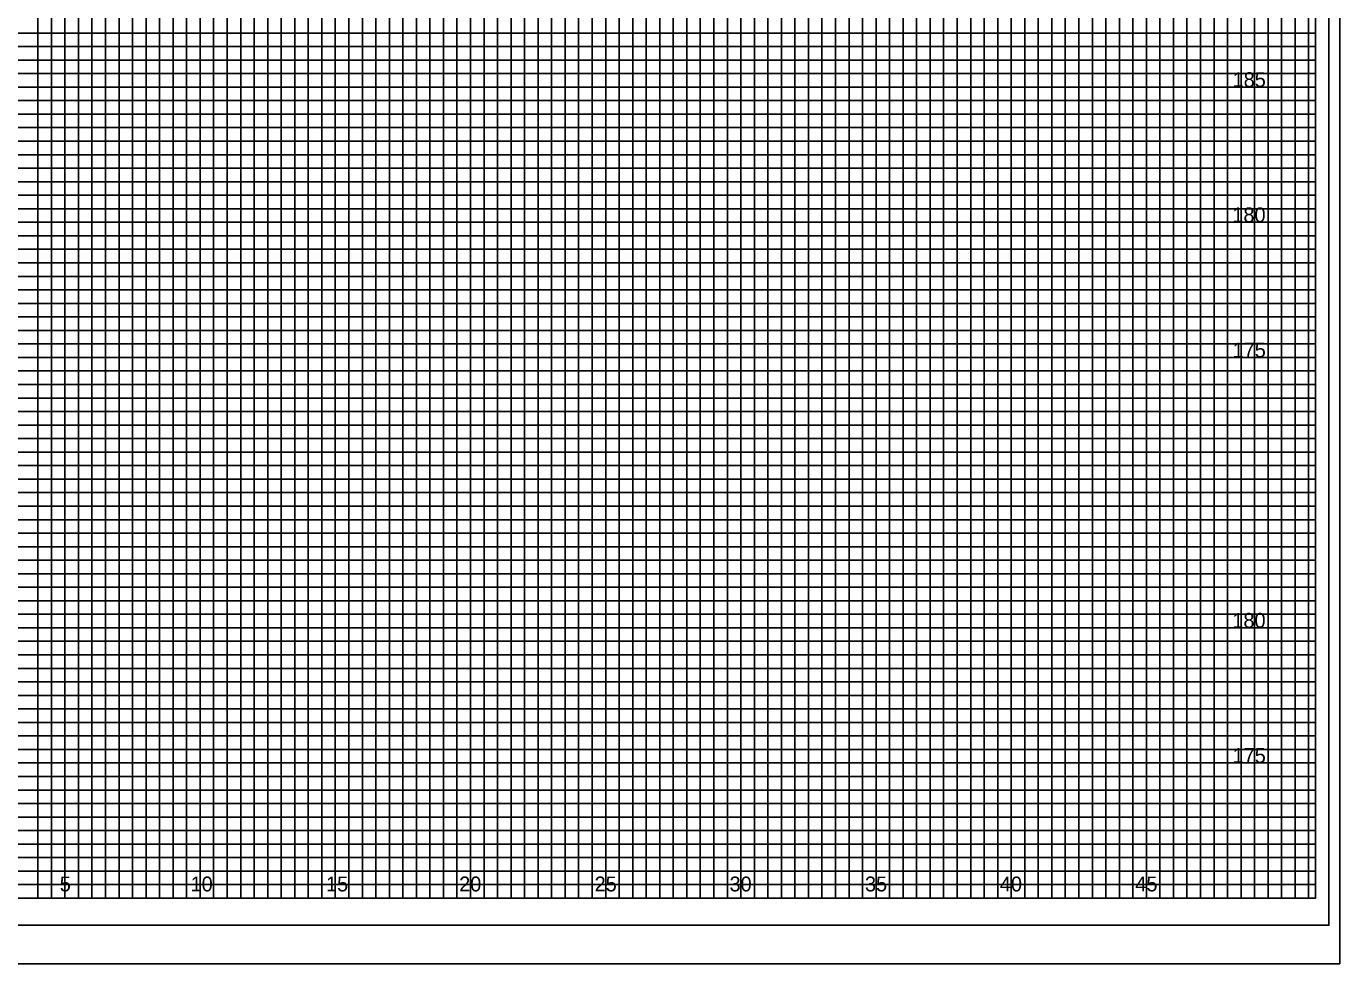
# Model space of a CAD drawing. Extents: x -4 to 103, y -2 to 138.
# Drawn here: x 54.82 to 103.4, y 68.4 to 103.08 of the extents above; entities that cross this region are included whole.
import ezdxf

# ---------------------------------------------------------------- set-up
doc = ezdxf.new("R2010")
doc.units = 0
for name, color, linetype in [('Old_Level_10', 7, 'Continuous'), ('Old_Level_3', 7, 'Continuous'), ('Old_Level_4', 7, 'Continuous'), ('Old_Level_5', 7, 'Continuous'), ('Old_Level_8', 7, 'Continuous'), ('Prop XS Elevation Labels', 7, 'Continuous'), ('Prop XS EOT Tick Mark', 7, 'Continuous'), ('Prop XS Finish Grade', 7, 'Continuous'), ('Prop XS Finish Grade Pavement', 7, 'Continuous')]:
    doc.layers.add(name, color=color, linetype=linetype)

msp = doc.modelspace()

# ---------------------------------------------------------------- linework, layer by layer
at = {"layer": 'Old_Level_10'}
for p, q in [((56.25, 70.825), (56.25, 135.825)), ((58.75, 70.825), (58.75, 135.825)), ((61.25, 70.825), (61.25, 135.825)), ((63.75, 70.825), (63.75, 135.825)), ((66.25, 70.825), (66.25, 135.825)), ((68.75, 70.825), (68.75, 135.825)), ((71.25, 70.825), (71.25, 135.825)), ((73.75, 70.825), (73.75, 135.825)), ((91.25, 70.825), (91.25, 134.25)), ((93.75, 70.825), (93.75, 134.25)), ((96.25, 70.825), (96.25, 134.25)), ((98.75, 70.825), (98.75, 134.25)), ((101.25, 70.825), (101.25, 134.25)), ((76.25, 70.825), (76.25, 132.825)), ((78.75, 70.825), (78.75, 132.825)), ((81.25, 70.825), (81.25, 132.825)), ((83.75, 70.825), (83.75, 132.825)), ((86.25, 70.825), (86.25, 132.825)), ((88.75, 70.825), (88.75, 132.825)), ((0, 100.825), (102.5, 100.825)), ((0, 98.325), (102.5, 98.325)), ((0, 95.825), (102.5, 95.825)), ((0, 93.325), (102.5, 93.325)), ((0, 90.825), (102.5, 90.825)), ((0, 88.325), (102.5, 88.325)), ((0, 85.825), (102.5, 85.825)), ((0, 83.325), (102.5, 83.325)), ((0, 80.825), (102.5, 80.825)), ((0, 78.325), (102.5, 78.325)), ((0, 75.825), (102.5, 75.825)), ((0, 73.325), (102.5, 73.325))]:
    msp.add_line(p, q, dxfattribs=at)
at = {"layer": 'Old_Level_3'}
msp.add_line((-3.5, 68.4), (103.4, 68.4), dxfattribs=at)
at = {"layer": 'Old_Level_4'}
msp.add_lwpolyline([(103, 136.825), (-2.8, 136.825), (-2.8, 69.825), (103, 69.825)], close=True, dxfattribs=at)
at = {"layer": 'Old_Level_5'}
msp.add_lwpolyline([(103.4, 138.225), (-3.5, 138.225), (-3.5, 68.4), (103.4, 68.4)], close=True, dxfattribs=at)
at = {"layer": 'Old_Level_8'}
for points in [[(56.25, 70.825), (56.25, 135.825)], [(58.75, 135.825), (58.75, 70.825), (61.25, 70.825), (61.25, 135.825)], [(63.75, 135.825), (63.75, 70.825), (66.25, 70.825), (66.25, 135.825)], [(68.75, 135.825), (68.75, 70.825), (71.25, 70.825), (71.25, 135.825)], [(73.75, 135.825), (73.75, 70.825), (76.25, 70.825), (76.25, 132.825)], [(88.75, 132.825), (88.75, 70.825), (91.25, 70.825), (91.25, 134.25)], [(93.75, 134.25), (93.75, 70.825), (96.25, 70.825), (96.25, 134.25)], [(98.75, 134.25), (98.75, 70.825), (101.25, 70.825), (101.25, 134.25)], [(78.75, 132.825), (78.75, 70.825), (81.25, 70.825), (81.25, 132.825)], [(83.75, 132.825), (83.75, 70.825), (86.25, 70.825), (86.25, 132.825)], [(0, 98.325), (102.5, 98.325), (102.5, 100.825), (0, 100.825)], [(0, 93.325), (102.5, 93.325), (102.5, 95.825), (0, 95.825)], [(0, 88.325), (102.5, 88.325), (102.5, 90.825), (0, 90.825)], [(0, 83.325), (102.5, 83.325), (102.5, 85.825), (0, 85.825)], [(0, 78.325), (102.5, 78.325), (102.5, 80.825), (0, 80.825)], [(0, 73.325), (102.5, 73.325), (102.5, 75.825), (0, 75.825)]]:
    msp.add_lwpolyline(points, dxfattribs=at)
at = {"layer": 'Prop XS Elevation Labels'}
msp.add_lwpolyline([(102.5, 135.825), (0, 135.825), (0, 70.825), (102.5, 70.825)], close=True, dxfattribs=at)
at = {"layer": 'Prop XS Finish Grade'}
for points in [[(54.75, 70.825), (55.25, 70.825), (55.25, 135.825)], [(55.75, 135.825), (55.75, 70.825), (56.75, 70.825), (56.75, 135.825)], [(57.25, 135.825), (57.25, 70.825), (57.75, 70.825), (57.75, 135.825)], [(58.25, 135.825), (58.25, 70.825), (59.25, 70.825), (59.25, 135.825)], [(59.75, 135.825), (59.75, 70.825), (60.25, 70.825), (60.25, 135.825)], [(60.75, 135.825), (60.75, 70.825), (61.75, 70.825), (61.75, 135.825)], [(62.25, 135.825), (62.25, 70.825), (62.75, 70.825), (62.75, 135.825)], [(63.25, 135.825), (63.25, 70.825), (64.25, 70.825), (64.25, 135.825)], [(64.75, 135.825), (64.75, 70.825), (65.25, 70.825), (65.25, 135.825)], [(65.75, 135.825), (65.75, 70.825), (66.75, 70.825), (66.75, 135.825)], [(67.25, 135.825), (67.25, 70.825), (67.75, 70.825), (67.75, 135.825)], [(68.25, 135.825), (68.25, 70.825), (69.25, 70.825), (69.25, 135.825)], [(69.75, 135.825), (69.75, 70.825), (70.25, 70.825), (70.25, 135.825)], [(70.75, 135.825), (70.75, 70.825), (71.75, 70.825), (71.75, 135.825)], [(72.25, 135.825), (72.25, 70.825), (72.75, 70.825), (72.75, 135.825)], [(73.25, 135.825), (73.25, 70.825), (74.25, 70.825), (74.25, 132.825)], [(89.75, 132.825), (89.75, 70.825), (90.25, 70.825), (90.25, 134.25)], [(90.75, 134.25), (90.75, 70.825), (91.75, 70.825), (91.75, 134.25)], [(92.25, 134.25), (92.25, 70.825), (92.75, 70.825), (92.75, 134.25)], [(93.25, 134.25), (93.25, 70.825), (94.25, 70.825), (94.25, 134.25)], [(94.75, 134.25), (94.75, 70.825), (95.25, 70.825), (95.25, 134.25)], [(95.75, 134.25), (95.75, 70.825), (96.75, 70.825), (96.75, 134.25)], [(97.25, 134.25), (97.25, 70.825), (97.75, 70.825), (97.75, 134.25)], [(98.25, 134.25), (98.25, 70.825), (99.25, 70.825), (99.25, 134.25)], [(99.75, 134.25), (99.75, 70.825), (100.25, 70.825), (100.25, 134.25)], [(100.25, 134.25), (100.75, 134.25), (100.75, 70.825), (101.75, 70.825), (101.75, 134.25), (102.25, 134.25), (102.25, 70.825)], [(74.75, 132.825), (74.75, 70.825), (75.25, 70.825), (75.25, 132.825)], [(75.75, 132.825), (75.75, 70.825), (76.75, 70.825), (76.75, 132.825)], [(77.25, 132.825), (77.25, 70.825), (77.75, 70.825), (77.75, 132.825)], [(78.25, 132.825), (78.25, 70.825), (79.25, 70.825), (79.25, 132.825)], [(79.75, 132.825), (79.75, 70.825), (80.25, 70.825), (80.25, 132.825)], [(80.75, 132.825), (80.75, 70.825), (81.75, 70.825), (81.75, 132.825)], [(82.25, 132.825), (82.25, 70.825), (82.75, 70.825), (82.75, 132.825)], [(83.25, 132.825), (83.25, 70.825), (84.25, 70.825), (84.25, 132.825)], [(84.75, 132.825), (84.75, 70.825), (85.25, 70.825), (85.25, 132.825)], [(85.75, 132.825), (85.75, 70.825), (86.75, 70.825), (86.75, 132.825)], [(87.25, 132.825), (87.25, 70.825), (87.75, 70.825), (87.75, 132.825)], [(88.25, 132.825), (88.25, 70.825), (89.25, 70.825), (89.25, 132.825)], [(0, 102.325), (102.5, 102.325), (102.5, 102.825), (0, 102.825)], [(0, 101.325), (102.5, 101.325), (102.5, 101.825), (0, 101.825)], [(0, 99.825), (102.5, 99.825), (102.5, 100.325), (0, 100.325)], [(0, 98.825), (102.5, 98.825), (102.5, 99.325), (0, 99.325)], [(0, 97.325), (102.5, 97.325), (102.5, 97.825), (0, 97.825)], [(0, 96.325), (102.5, 96.325), (102.5, 96.825), (0, 96.825)], [(0, 94.825), (102.5, 94.825), (102.5, 95.325), (0, 95.325)], [(0, 93.825), (102.5, 93.825), (102.5, 94.325), (0, 94.325)], [(0, 92.325), (102.5, 92.325), (102.5, 92.825), (0, 92.825)], [(0, 91.325), (102.5, 91.325), (102.5, 91.825), (0, 91.825)], [(0, 89.825), (102.5, 89.825), (102.5, 90.325), (0, 90.325)], [(0, 88.825), (102.5, 88.825), (102.5, 89.325), (0, 89.325)], [(0, 87.325), (102.5, 87.325), (102.5, 87.825), (0, 87.825)], [(0, 86.325), (102.5, 86.325), (102.5, 86.825), (0, 86.825)], [(0, 84.825), (102.5, 84.825), (102.5, 85.325), (0, 85.325)], [(0, 83.825), (102.5, 83.825), (102.5, 84.325), (0, 84.325)], [(0, 82.325), (102.5, 82.325), (102.5, 82.825), (0, 82.825)], [(0, 81.325), (102.5, 81.325), (102.5, 81.825), (0, 81.825)], [(0, 79.825), (102.5, 79.825), (102.5, 80.325), (0, 80.325)], [(0, 78.825), (102.5, 78.825), (102.5, 79.325), (0, 79.325)], [(0, 77.325), (102.5, 77.325), (102.5, 77.825), (0, 77.825)], [(0, 76.325), (102.5, 76.325), (102.5, 76.825), (0, 76.825)], [(0, 74.825), (102.5, 74.825), (102.5, 75.325), (0, 75.325)], [(0, 73.825), (102.5, 73.825), (102.5, 74.325), (0, 74.325)], [(0, 72.325), (102.5, 72.325), (102.5, 72.825), (0, 72.825)], [(0, 71.325), (102.5, 71.325), (102.5, 71.825), (0, 71.825)]]:
    msp.add_lwpolyline(points, dxfattribs=at)

# ---------------------------------------------------------------- texts
at = {"layer": 'Prop XS EOT Tick Mark'}
for s, p in [('185', (99.438, 100.825)), ('180', (99.43, 95.825)), ('175', (99.438, 90.825)), ('180', (99.43, 80.825)), ('175', (99.438, 75.825))]:
    msp.add_text(s, height=0.55, dxfattribs=at).set_placement(p)
at = {"layer": 'Prop XS Finish Grade Pavement'}
for s, p in [('5', (56.057, 71.075)), ('10', (60.897, 71.075)), ('15', (65.906, 71.075)), ('20', (70.831, 71.075)), ('25', (75.84, 71.075)), ('30', (80.831, 71.075)), ('35', (85.84, 71.075)), ('40', (90.831, 71.075)), ('45', (95.84, 71.075))]:
    msp.add_text(s, height=0.55, dxfattribs=at).set_placement(p)

doc.saveas('drawing.dxf')
